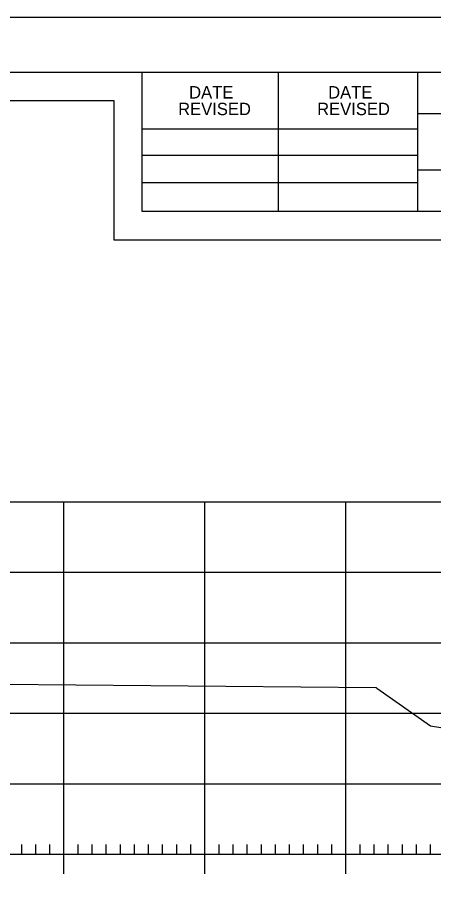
# Model space of a CAD drawing. Extents: x 1368910 to 1369601, y 380116 to 380950.
# Drawn here: x 1369524.3 to 1369553.8, y 380462.3 to 380523.8 of the extents above; entities that cross this region are included whole.
import ezdxf

# ---------------------------------------------------------------- set-up
doc = ezdxf.new("R2010")
doc.units = 0
for name, color, linetype in [('R_Axis', 7, 'Continuous'), ('R_Border', 7, 'Continuous'), ('R_Exist Surface', 7, 'Continuous'), ('R_Grid', 7, 'Continuous'), ('R_No Plot', 7, 'Continuous')]:
    doc.layers.add(name, color=color, linetype=linetype)

msp = doc.modelspace()

# ---------------------------------------------------------------- linework, layer by layer
at = {"layer": 'R_Axis'}
for p, q in [((1369527.59, 380463.021), (1369527.59, 380465.821)), ((1369537.59, 380463.021), (1369537.59, 380465.821)), ((1369547.59, 380463.021), (1369547.59, 380465.821)), ((1369524.59, 380464.421), (1369524.59, 380465.121)), ((1369525.59, 380464.421), (1369525.59, 380465.121)), ((1369526.59, 380464.421), (1369526.59, 380465.121)), ((1369528.59, 380464.421), (1369528.59, 380465.121)), ((1369529.59, 380464.421), (1369529.59, 380465.121)), ((1369530.59, 380464.421), (1369530.59, 380465.121)), ((1369531.59, 380464.421), (1369531.59, 380465.121)), ((1369532.59, 380464.421), (1369532.59, 380465.121)), ((1369533.59, 380464.421), (1369533.59, 380465.121)), ((1369534.59, 380464.421), (1369534.59, 380465.121)), ((1369535.59, 380464.421), (1369535.59, 380465.121)), ((1369536.59, 380464.421), (1369536.59, 380465.121)), ((1369538.59, 380464.421), (1369538.59, 380465.121)), ((1369539.59, 380464.421), (1369539.59, 380465.121)), ((1369540.59, 380464.421), (1369540.59, 380465.121)), ((1369541.59, 380464.421), (1369541.59, 380465.121)), ((1369542.59, 380464.421), (1369542.59, 380465.121)), ((1369543.59, 380464.421), (1369543.59, 380465.121)), ((1369544.59, 380464.421), (1369544.59, 380465.121)), ((1369545.59, 380464.421), (1369545.59, 380465.121)), ((1369546.59, 380464.421), (1369546.59, 380465.121)), ((1369548.59, 380464.421), (1369548.59, 380465.121)), ((1369549.59, 380464.421), (1369549.59, 380465.121)), ((1369550.59, 380464.421), (1369550.59, 380465.121)), ((1369551.59, 380464.421), (1369551.59, 380465.121)), ((1369552.59, 380464.421), (1369552.59, 380465.121)), ((1369553.59, 380464.421), (1369553.59, 380465.121)), ((1369297.59, 380464.421), (1369577.59, 380464.421))]:
    msp.add_line(p, q, dxfattribs=at)
at = {"layer": 'R_Border'}
for p, q in [((1369279.59, 380519.881), (1369595.77, 380519.881)), ((1369533.13, 380510.001), (1369533.13, 380519.881)), ((1369542.81, 380510.001), (1369542.81, 380519.881)), ((1369552.67, 380519.881), (1369552.67, 380510.001)), ((1369595.77, 380516.941), (1369552.67, 380516.941)), ((1369533.13, 380515.861), (1369552.67, 380515.861)), ((1369533.13, 380514.001), (1369552.67, 380514.001)), ((1369595.77, 380512.941), (1369552.67, 380512.941)), ((1369533.13, 380512.061), (1369552.67, 380512.061)), ((1369595.77, 380510.001), (1369533.13, 380510.001))]:
    msp.add_line(p, q, dxfattribs=at)
at = {"layer": 'R_Exist Surface'}
msp.add_lwpolyline([(1369523.111, 380476.473), (1369549.701, 380476.252), (1369549.725, 380476.253), (1369549.738, 380476.255), (1369549.774, 380476.194), (1369553.587, 380473.527), (1369556.799, 380473.017), (1369559.991, 380473.431), (1369564.938, 380473.265), (1369575.777, 380473.406), (1369577.59, 380473.534)], dxfattribs=at)
at = {"layer": 'R_Grid'}
for p, q in [((1369297.59, 380489.421), (1369577.59, 380489.421)), ((1369527.59, 380464.421), (1369527.59, 380489.421)), ((1369537.59, 380464.421), (1369537.59, 380489.421)), ((1369547.59, 380464.421), (1369547.59, 380489.421)), ((1369297.59, 380484.421), (1369577.59, 380484.421)), ((1369297.59, 380479.421), (1369577.59, 380479.421)), ((1369297.59, 380474.421), (1369577.59, 380474.421)), ((1369297.59, 380469.421), (1369577.59, 380469.421)), ((1369297.59, 380464.421), (1369577.59, 380464.421))]:
    msp.add_line(p, q, dxfattribs=at)
at = {"layer": 'R_No Plot'}
for points in [[(1369267.182, 380523.775), (1369600.522, 380523.775), (1369600.522, 380310.438), (1369267.182, 380310.438)], [(1369593.77, 380419.151), (1369281.59, 380419.151), (1369281.59, 380517.881), (1369531.13, 380517.881), (1369531.13, 380508.001), (1369548.67, 380508.001), (1369572.77, 380508.001), (1369572.77, 380485.668), (1369593.77, 380485.668)], [(1369281.59, 380517.881), (1369531.13, 380517.881), (1369531.13, 380508.001), (1369548.67, 380508.001), (1369572.77, 380508.001), (1369572.77, 380485.668), (1369593.77, 380485.668), (1369593.77, 380316.421), (1369281.59, 380316.421)]]:
    msp.add_lwpolyline(points, close=True, dxfattribs=at)

# ---------------------------------------------------------------- texts
at = {"layer": 'R_Border'}
for s, p in [('DATE', (1369536.468, 380518.017)), ('DATE', (1369546.328, 380518.017)), ('REVISED', (1369535.688, 380516.837)), ('REVISED', (1369545.548, 380516.837))]:
    msp.add_text(s, height=0.8792, dxfattribs=at).set_placement(p)

doc.saveas('drawing.dxf')
